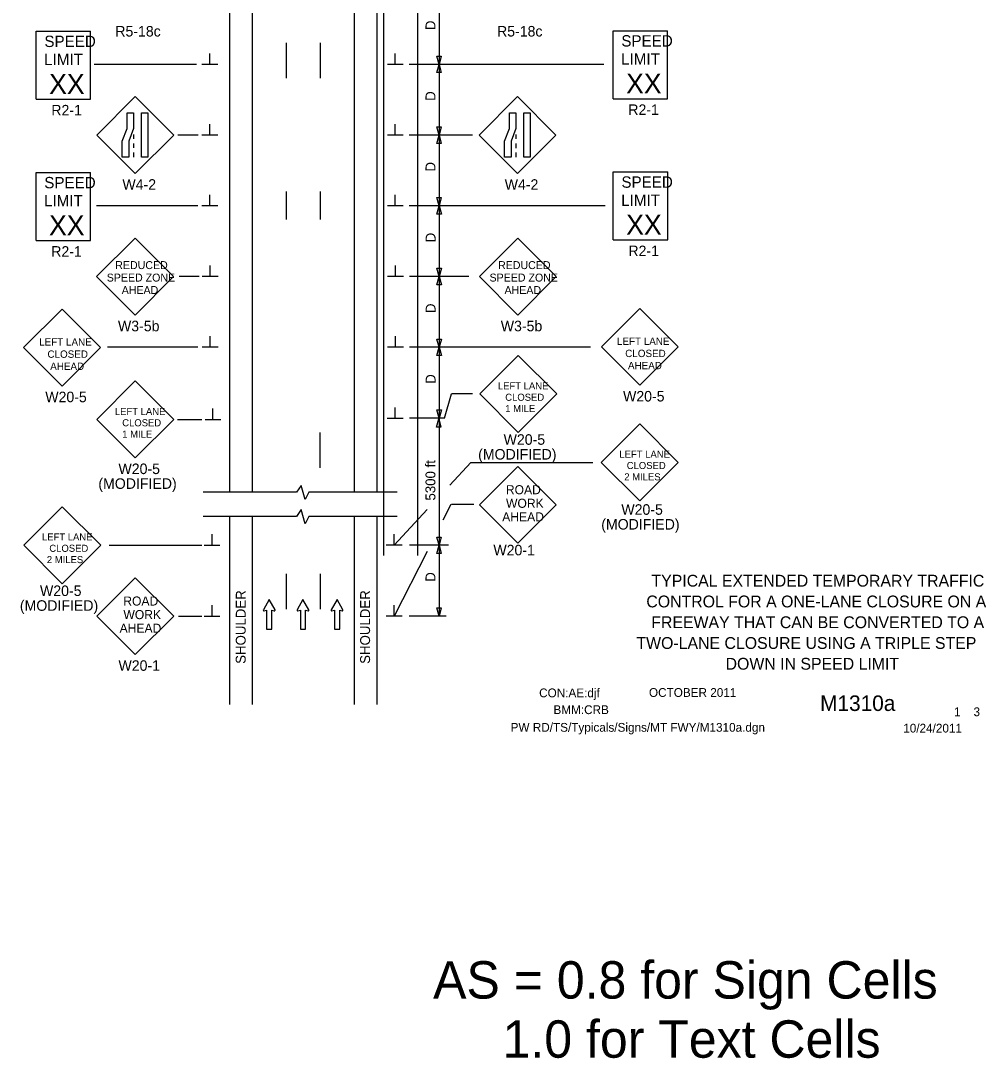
# Model space of a CAD drawing. Extents: x 16724 to 19508, y 5703 to 6974.
# Drawn here: x 16724 to 17407, y 5703 to 6436 of the extents above; entities that cross this region are included whole.
import ezdxf

# ---------------------------------------------------------------- set-up
doc = ezdxf.new("R2010")
doc.units = 0
for name, color, linetype in [('ALI_LEGAL_EX', 7, 'Continuous'), ('BORDER', 7, 'Continuous'), ('BORDER_SIGNAL_WO', 7, 'Continuous'), ('Level 3', 7, 'Continuous'), ('MT_SCRATCH_LEVEL_E', 7, 'Continuous'), ('PAVT_EDGE_EX', 7, 'Continuous'), ('TRAFFIC_SIGNS_PR', 7, 'Continuous'), ('TYPICAL_TEXT_DIMEN_PR', 7, 'Continuous')]:
    doc.layers.add(name, color=color, linetype=linetype)

msp = doc.modelspace()

# ---------------------------------------------------------------- linework, layer by layer
at = {"layer": 'ALI_LEGAL_EX'}
for p, q in [((16980.68, 6974.12), (16980.68, 6155.98)), ((17004.68, 6974.12), (17004.68, 6155.98)), ((16980.68, 6922.21), (16980.68, 6058.3)), ((17004.68, 6922.21), (17004.68, 6058.3))]:
    msp.add_line(p, q, dxfattribs=at)
for points in [[(16911.96, 6420.69), (16911.96, 6395.69)], [(16935.96, 6420.69), (16935.96, 6395.69)], [(16911.96, 6315.64), (16911.96, 6295.69)], [(16935.96, 6315.64), (16935.96, 6295.69)], [(16935.96, 6120.25), (16935.96, 6145.25)], [(16911.96, 6045.25), (16911.96, 6020.25)], [(16935.96, 6045.25), (16935.96, 6020.25)]]:
    msp.add_lwpolyline(points, dxfattribs=at)
at = {"layer": 'Level 3'}
msp.add_line((17023.76, 6155.41), (17028.75, 6172.5), dxfattribs=at)
at = {"layer": 'MT_SCRATCH_LEVEL_E'}
for p, q in [((16899.96, 6027.15), (16895.85, 6019.91)), ((16904.1, 6019.91), (16899.96, 6027.15)), ((16923.86, 6027.15), (16919.75, 6019.91)), ((16928.01, 6019.91), (16923.86, 6027.15)), ((16947.91, 6027.15), (16943.8, 6019.91)), ((16952.06, 6019.91), (16947.91, 6027.15)), ((16896.33, 6019.23), (16898.1, 6019.54)), ((16898.1, 6019.54), (16898.1, 6006.28)), ((16901.85, 6006.28), (16901.85, 6019.54)), ((16901.85, 6019.54), (16903.62, 6019.23)), ((16920.23, 6019.23), (16922.01, 6019.54)), ((16922.01, 6019.54), (16922.01, 6006.28)), ((16925.75, 6006.28), (16925.75, 6019.54)), ((16925.75, 6019.54), (16927.53, 6019.23)), ((16944.28, 6019.23), (16946.06, 6019.54)), ((16946.06, 6019.54), (16946.06, 6006.28)), ((16949.8, 6006.28), (16949.8, 6019.54)), ((16949.8, 6019.54), (16951.58, 6019.23)), ((16898.1, 6006.28), (16901.85, 6006.28)), ((16922.01, 6006.28), (16925.75, 6006.28)), ((16946.06, 6006.28), (16949.8, 6006.28))]:
    msp.add_line(p, q, dxfattribs=at)
for centre, start, end in [((16896.25, 6019.68), 150.42484, 279.96381), ((16903.69, 6019.68), 260.03619, 29.77312), ((16920.16, 6019.68), 150.42484, 279.96381), ((16927.6, 6019.68), 260.03619, 29.77312), ((16944.21, 6019.68), 150.42484, 279.96381), ((16951.65, 6019.68), 260.03619, 29.77312)]:
    msp.add_arc(centre, 0.463, start, end, dxfattribs=at)
at = {"layer": 'PAVT_EDGE_EX'}
for p, q in [((16871.96, 6927.73), (16871.96, 6180.21)), ((16887.96, 6927.73), (16887.96, 6180.21)), ((16959.96, 6927.73), (16959.96, 6180.21)), ((16975.96, 6927.73), (16975.96, 6180.21)), ((16871.96, 6180.21), (16871.96, 6103.04)), ((16887.96, 6180.21), (16887.96, 6103.06)), ((16959.96, 6180.21), (16959.96, 6103.06)), ((16975.96, 6180.21), (16975.96, 6103.06)), ((16871.96, 6085.92), (16871.96, 5952.9)), ((16887.96, 6085.92), (16887.96, 5952.9)), ((16959.96, 6085.92), (16959.96, 5952.9)), ((16975.96, 6085.92), (16975.96, 5952.9))]:
    msp.add_line(p, q, dxfattribs=at)
at = {"layer": 'TRAFFIC_SIGNS_PR'}
for p, q in [((16735.39, 6428.82), (16773.84, 6428.82)), ((16735.39, 6380.76), (16735.39, 6428.82)), ((16773.84, 6380.76), (16773.84, 6428.82)), ((17143.01, 6429.16), (17181.45, 6429.16)), ((17143.01, 6381.1), (17143.01, 6429.16)), ((17181.45, 6381.1), (17181.45, 6429.16)), ((16735.39, 6380.76), (16773.84, 6380.76)), ((16805.32, 6382.63), (16778.14, 6355.44)), ((16832.51, 6355.44), (16805.32, 6382.63)), ((17075.42, 6382.59), (17048.23, 6355.4)), ((17102.6, 6355.4), (17075.42, 6382.59)), ((17143.01, 6381.1), (17181.45, 6381.1)), ((16778.14, 6355.44), (16805.32, 6328.26)), ((16804.07, 6355.93), (16804.07, 6352.73)), ((16805.32, 6328.26), (16832.51, 6355.44)), ((17048.23, 6355.4), (17075.42, 6328.22)), ((17074.17, 6355.89), (17074.17, 6352.69)), ((17075.42, 6328.22), (17102.6, 6355.4)), ((16804.07, 6349.53), (16804.07, 6346.32)), ((16804.07, 6343.12), (16804.07, 6339.91)), ((17074.17, 6349.49), (17074.17, 6346.28)), ((17074.17, 6343.08), (17074.17, 6339.87)), ((16735.31, 6328.98), (16773.76, 6328.98)), ((16735.31, 6280.91), (16735.31, 6328.98)), ((16773.76, 6280.91), (16773.76, 6328.98)), ((17143.07, 6329.36), (17181.52, 6329.36)), ((17143.07, 6281.3), (17143.07, 6329.36)), ((17181.52, 6281.3), (17181.52, 6329.36)), ((16735.31, 6280.91), (16773.76, 6280.91)), ((16805.19, 6282.58), (16778, 6255.4)), ((16832.38, 6255.4), (16805.19, 6282.58)), ((17075.64, 6282.58), (17048.45, 6255.4)), ((17102.83, 6255.4), (17075.64, 6282.58)), ((17143.07, 6281.3), (17181.52, 6281.3)), ((16778, 6255.4), (16805.19, 6228.21)), ((16805.19, 6228.21), (16832.38, 6255.4)), ((17048.45, 6255.4), (17075.64, 6228.21)), ((17075.64, 6228.21), (17102.83, 6255.4)), ((16753.63, 6232.36), (16726.48, 6205.21)), ((16780.78, 6205.21), (16753.63, 6232.36)), ((17161.81, 6232.87), (17134.65, 6205.72)), ((17188.96, 6205.72), (17161.81, 6232.87)), ((16726.48, 6205.21), (16753.63, 6178.06)), ((16753.63, 6178.06), (16780.78, 6205.21)), ((17134.65, 6205.72), (17161.81, 6178.56)), ((17161.81, 6178.56), (17188.96, 6205.72)), ((17075.92, 6199.69), (17048.73, 6172.5)), ((17103.1, 6172.5), (17075.92, 6199.69)), ((16805.33, 6181.65), (16778.14, 6154.46)), ((16832.52, 6154.46), (16805.33, 6181.65)), ((17048.73, 6172.5), (17075.92, 6145.32)), ((17075.92, 6145.32), (17103.1, 6172.5)), ((16778.14, 6154.46), (16805.33, 6127.28)), ((16805.33, 6127.28), (16832.52, 6154.46)), ((17161.77, 6151.23), (17134.58, 6124.04)), ((17188.96, 6124.04), (17161.77, 6151.23)), ((17134.58, 6124.04), (17161.77, 6096.86)), ((17161.77, 6096.86), (17188.96, 6124.04)), ((17075.64, 6121.2), (17048.49, 6094.04)), ((17102.79, 6094.04), (17075.64, 6121.2)), ((17048.49, 6094.04), (17075.64, 6066.89)), ((17075.64, 6066.89), (17102.79, 6094.04)), ((16753.83, 6092.71), (16726.64, 6065.53)), ((16781.01, 6065.53), (16753.83, 6092.71)), ((16726.64, 6065.53), (16753.83, 6038.34)), ((16753.83, 6038.34), (16781.01, 6065.53)), ((16805.34, 6042.51), (16778.19, 6015.35)), ((16832.5, 6015.35), (16805.34, 6042.51)), ((16778.19, 6015.35), (16805.34, 5988.2)), ((16805.34, 5988.2), (16832.5, 6015.35))]:
    msp.add_line(p, q, dxfattribs=at)
for points in [[(16804.07, 6371.2), (16804.07, 6360), (16800.73, 6351.11), (16800.73, 6339.91), (16796.23, 6339.91), (16796.23, 6351.11), (16799.57, 6360), (16799.57, 6371.2)], [(16814.22, 6371.2), (16814.22, 6339.91), (16809.72, 6339.91), (16809.72, 6371.2)], [(17074.17, 6371.16), (17074.17, 6359.96), (17070.82, 6351.07), (17070.82, 6339.87), (17066.32, 6339.87), (17066.32, 6351.07), (17069.67, 6359.96), (17069.67, 6371.16)], [(17084.32, 6371.16), (17084.32, 6339.87), (17079.82, 6339.87), (17079.82, 6371.16)]]:
    msp.add_lwpolyline(points, close=True, dxfattribs=at)
at = {"layer": 'TYPICAL_TEXT_DIMEN_PR'}
for p, q in [((17019.96, 6455.41), (17019.96, 6405.41)), ((16858.07, 6405.41), (16858.07, 6413.19)), ((16989.08, 6405.41), (16989.08, 6413.19)), ((17019.96, 6405.41), (17018.39, 6411.27)), ((17018.39, 6411.27), (17019.96, 6411.27)), ((17019.96, 6411.27), (17021.53, 6411.27)), ((17021.53, 6411.27), (17019.96, 6405.41)), ((16848.73, 6405.41), (16776.3, 6405.41)), ((16863.7, 6405.41), (16852.45, 6405.41)), ((16994.71, 6405.41), (16983.46, 6405.41)), ((17027.77, 6405.41), (16998.96, 6405.41)), ((17018.39, 6399.55), (17019.96, 6405.41)), ((17019.96, 6405.41), (17019.96, 6355.41)), ((17019.96, 6405.41), (17021.53, 6399.55)), ((17136.33, 6405.41), (17027.77, 6405.41)), ((17019.96, 6399.55), (17018.39, 6399.55)), ((17021.53, 6399.55), (17019.96, 6399.55)), ((16858.07, 6355.41), (16858.07, 6363.19)), ((16989.08, 6355.41), (16989.08, 6363.19)), ((17019.96, 6355.41), (17018.39, 6361.27)), ((17018.39, 6361.27), (17019.96, 6361.27)), ((17019.96, 6361.27), (17021.53, 6361.27)), ((17021.53, 6361.27), (17019.96, 6355.41)), ((16849.89, 6355.41), (16835.47, 6355.41)), ((16863.7, 6355.41), (16852.45, 6355.41)), ((16994.71, 6355.41), (16983.46, 6355.41)), ((17027.77, 6355.41), (16998.96, 6355.41)), ((17018.39, 6349.55), (17019.96, 6355.41)), ((17019.96, 6355.41), (17019.96, 6305.41)), ((17019.96, 6355.41), (17021.53, 6349.55)), ((17043.6, 6355.41), (17027.77, 6355.41)), ((17019.96, 6349.55), (17018.39, 6349.55)), ((17021.53, 6349.55), (17019.96, 6349.55)), ((16858.07, 6305.41), (16858.07, 6313.19)), ((16989.08, 6305.41), (16989.08, 6313.19)), ((17019.96, 6305.41), (17018.39, 6311.27)), ((17018.39, 6311.27), (17019.96, 6311.27)), ((17019.96, 6311.27), (17021.53, 6311.27)), ((17021.53, 6311.27), (17019.96, 6305.41)), ((16849.6, 6305.41), (16777.95, 6305.41)), ((16863.7, 6305.41), (16852.45, 6305.41)), ((16994.71, 6305.41), (16983.46, 6305.41)), ((17027.77, 6305.41), (16998.96, 6305.41)), ((17018.52, 6299.55), (17020.09, 6305.41)), ((17020.09, 6299.55), (17018.52, 6299.55)), ((17020.09, 6305.41), (17020.09, 6255.41)), ((17020.09, 6305.41), (17021.66, 6299.55)), ((17021.66, 6299.55), (17020.09, 6299.55)), ((17137.25, 6305.41), (17027.77, 6305.41)), ((16858.21, 6255.41), (16858.21, 6263.19)), ((16989.22, 6255.41), (16989.22, 6263.19)), ((16850.42, 6255.41), (16836.41, 6255.41)), ((16863.83, 6255.41), (16852.58, 6255.41)), ((16994.84, 6255.41), (16983.59, 6255.41)), ((17027.77, 6255.41), (16999.09, 6255.41)), ((17020.09, 6255.41), (17018.52, 6261.27)), ((17018.52, 6261.27), (17020.09, 6261.27)), ((17018.52, 6249.55), (17020.09, 6255.41)), ((17020.09, 6261.27), (17021.66, 6261.27)), ((17021.66, 6261.27), (17020.09, 6255.41)), ((17020.09, 6255.41), (17020.09, 6205.41)), ((17020.09, 6255.41), (17021.66, 6249.55)), ((17040.96, 6255.41), (17027.77, 6255.41)), ((17020.09, 6249.55), (17018.52, 6249.55)), ((17021.66, 6249.55), (17020.09, 6249.55)), ((16858.21, 6205.41), (16858.21, 6213.19)), ((16989.22, 6205.41), (16989.22, 6213.19)), ((17020.09, 6205.41), (17018.52, 6211.27)), ((17018.52, 6211.27), (17020.09, 6211.27)), ((17020.09, 6211.27), (17021.66, 6211.27)), ((17021.66, 6211.27), (17020.09, 6205.41)), ((16849.51, 6205.41), (16785.69, 6205.41)), ((16863.83, 6205.41), (16852.58, 6205.41)), ((16994.84, 6205.41), (16983.59, 6205.41)), ((17027.77, 6205.41), (16999.09, 6205.41)), ((17018.52, 6199.55), (17020.09, 6205.41)), ((17020.09, 6205.41), (17020.09, 6155.41)), ((17020.09, 6205.41), (17021.66, 6199.55)), ((17127.09, 6205.41), (17027.77, 6205.41)), ((17020.09, 6199.55), (17018.52, 6199.55)), ((17021.66, 6199.55), (17020.09, 6199.55)), ((17043.57, 6172.5), (17028.75, 6172.5)), ((16860.27, 6154.5), (16860.27, 6162.28)), ((16989.05, 6155.07), (16989.05, 6162.85)), ((17020.09, 6155.41), (17018.52, 6161.27)), ((17018.52, 6161.27), (17020.09, 6161.27)), ((17020.09, 6161.27), (17021.66, 6161.27)), ((17021.66, 6161.27), (17020.09, 6155.41)), ((16835.24, 6154.5), (16852.43, 6154.5)), ((16854.64, 6154.5), (16865.89, 6154.5)), ((16994.67, 6155.07), (16983.42, 6155.07)), ((17023.76, 6155.41), (16999.09, 6155.41)), ((17018.22, 6149), (17019.79, 6154.86)), ((17019.79, 6154.86), (17021.36, 6149)), ((17019.96, 6155.41), (17019.96, 6065.48)), ((17019.79, 6149), (17018.22, 6149)), ((17021.36, 6149), (17019.79, 6149)), ((17027.71, 6108.01), (17042.51, 6124)), ((17042.51, 6124), (17128.69, 6124)), ((16919.31, 6103.04), (16853.36, 6103.04)), ((16922.56, 6107.84), (16919.31, 6103.04)), ((16925.3, 6097.9), (16922.56, 6107.84)), ((16928.05, 6103.04), (16925.3, 6097.9)), ((16990.38, 6103.04), (16928.05, 6103.04)), ((17028.38, 6094.23), (17022.75, 6083.16)), ((17044.62, 6094.23), (17028.8, 6094.23)), ((16922.56, 6090.71), (16919.31, 6085.91)), ((16925.3, 6080.77), (16922.56, 6090.71)), ((16988.33, 6065.48), (17011.66, 6090.68)), ((16919.31, 6085.91), (16853.36, 6085.91)), ((16928.05, 6085.91), (16925.3, 6080.77)), ((16990.38, 6085.91), (16928.05, 6085.91)), ((16859.58, 6065.48), (16859.58, 6073.27)), ((16988.33, 6065.48), (16988.33, 6073.27)), ((16786.86, 6065.48), (16852.43, 6065.48)), ((16853.96, 6065.48), (16865.21, 6065.48)), ((16993.96, 6065.48), (16982.71, 6065.48)), ((17026.57, 6065.48), (16999.09, 6065.48)), ((17019.96, 6065.48), (17018.39, 6071.34)), ((17018.39, 6071.34), (17019.96, 6071.34)), ((17018.39, 6059.62), (17019.96, 6065.48)), ((17019.96, 6071.34), (17021.53, 6071.34)), ((17021.53, 6071.34), (17019.96, 6065.48)), ((17019.96, 6065.48), (17019.96, 6015.48)), ((17019.96, 6065.48), (17021.53, 6059.62)), ((17011.5, 6061.03), (16988.33, 6015.48)), ((17019.96, 6059.62), (17018.39, 6059.62)), ((17021.53, 6059.62), (17019.96, 6059.62)), ((16859.58, 6015.48), (16859.58, 6023.27)), ((16988.33, 6015.48), (16988.33, 6023.27)), ((17019.96, 6015.48), (17018.39, 6021.34)), ((17018.39, 6021.34), (17019.96, 6021.34)), ((17019.96, 6021.34), (17021.53, 6021.34)), ((17021.53, 6021.34), (17019.96, 6015.48)), ((16835.9, 6015.48), (16852.43, 6015.48)), ((16853.96, 6015.48), (16865.21, 6015.48)), ((16993.96, 6015.48), (16982.71, 6015.48)), ((17024.96, 6015.48), (16998.96, 6015.48))]:
    msp.add_line(p, q, dxfattribs=at)

# ---------------------------------------------------------------- texts
at = {"layer": 'BORDER'}
for s, p in [('TYPICAL EXTENDED TEMPORARY TRAFFIC', (17170.06, 6036.26)), ('CONTROL FOR A ONE-LANE CLOSURE ON A', (17166.43, 6021.59)), ('FREEWAY THAT CAN BE CONVERTED TO A', (17169.93, 6006.91)), ('TWO-LANE CLOSURE USING A TRIPLE STEP ', (17159.43, 5992.23)), ('DOWN IN SPEED LIMIT', (17222.43, 5977.56))]:
    msp.add_text(s, height=8.3734, dxfattribs=at).set_placement(p)
at = {"layer": 'BORDER_SIGNAL_WO'}
for s, height, p in [('CON:AE:djf  ', 6.2, (17090.69, 5958.06)), ('    OCTOBER 2011    ', 6.2, (17159.08, 5958.34)), ('    M1310a   ', 11, (17272.86, 5948.38)), ('BMM:CRB   ', 6.2, (17100.81, 5946.17)), (' 1    3 ', 6.2, (17381.45, 5944.7)), ('PW RD/TS/Typicals/Signs/MT FWY/M1310a.dgn      ', 6.2, (17070.55, 5933.71)), ('10/24/2011    ', 6.2, (17347.93, 5933.13)), ('AS = 0.8 for Sign Cells', 26.4241, (17015.79, 5745.09)), ('     1.0 for Text Cells', 26.4241, (17015.79, 5703.3))]:
    msp.add_text(s, height=height, dxfattribs=at).set_placement(p)
at = {"layer": 'TRAFFIC_SIGNS_PR'}
for s, height, p in [('R5-18c', 7.44, (16791.28, 6425.09)), ('R5-18c', 7.44, (17060.98, 6425.09)), ('SPEED', 8.01, (16741.17, 6417.67)), ('SPEED', 8.01, (17148.78, 6418.01)), ('LIMIT', 8.01, (16741.01, 6404.86)), ('LIMIT', 8.01, (17148.62, 6405.2)), ('XX', 14.048, (16744.52, 6384.53)), ('XX', 14.048, (17152.13, 6384.87)), ('R2-1', 7.449, (16746.08, 6369.31)), ('R2-1', 7.449, (17153.7, 6369.65)), ('SPEED', 8.01, (16741.09, 6317.82)), ('W4-2', 7.449, (16796.27, 6316.8)), ('W4-2', 7.449, (17066.36, 6316.76)), ('SPEED', 8.01, (17148.84, 6318.21)), ('LIMIT', 8.01, (16740.93, 6305.01)), ('LIMIT', 8.01, (17148.68, 6305.4)), ('XX', 14.048, (17152.19, 6285.07)), ('XX', 14.048, (16744.44, 6284.68)), ('R2-1', 7.449, (17153.76, 6269.85)), ('R2-1', 7.449, (16746, 6269.46)), ('REDUCED', 5.607, (16791.23, 6260.71)), ('REDUCED', 5.607, (17061.68, 6260.71)), ('SPEED ZONE', 5.607, (16785.21, 6251.9)), ('SPEED ZONE', 5.607, (17055.66, 6251.9)), ('AHEAD', 5.607, (16795.79, 6243.09)), ('AHEAD', 5.607, (17066.24, 6243.09)), ('W3-5b', 7.449, (16793.13, 6216.75)), ('W3-5b', 7.449, (17063.58, 6216.76)), ('LEFT LANE', 5.2, (16737.51, 6206.61)), ('LEFT LANE', 5.2, (17145.69, 6207.11)), ('CLOSED', 5.2, (17151.52, 6198.51)), ('CLOSED', 5.2, (16743.34, 6198.01)), ('AHEAD', 5.2, (16745.29, 6189.41)), ('AHEAD', 5.2, (17153.46, 6189.91)), ('LEFT LANE', 5.006, (17061.53, 6175.63)), ('W20-5', 7.44, (17149.98, 6167.12)), ('W20-5', 7.44, (16741.8, 6166.62)), ('CLOSED', 5.006, (17066.74, 6167.62)), ('LEFT LANE', 5.006, (16790.94, 6157.59)), ('1 MILE', 5.006, (17066.74, 6159.61)), ('CLOSED', 5.006, (16796.15, 6149.58)), ('1 MILE', 5.006, (16796.15, 6141.57)), ('W20-5 ', 7.449, (17065.59, 6136.53)), ('(MODIFIED) ', 7.4493, (17047.61, 6126.08)), ('LEFT LANE', 5.006, (17147.38, 6127.39)), ('W20-5', 7.449, (16793.49, 6115.82)), ('CLOSED', 5.006, (17152.59, 6119.39)), ('2 MILES', 5.006, (17150.84, 6111.38)), ('(MODIFIED)', 7.449, (16779.29, 6105.37)), ('ROAD', 6.4, (17067.18, 6101.58)), ('WORK', 6.4, (17067.29, 6091.98)), ('W20-5', 7.449, (17148.77, 6087.05)), ('AHEAD', 6.4, (17064.6, 6082.38)), ('(MODIFIED)', 7.449, (17134.58, 6076.6)), ('LEFT LANE', 5.006, (16739.43, 6068.88)), ('CLOSED', 5.006, (16744.65, 6060.87)), ('W20-1', 7.44, (17058.37, 6058.38)), ('2 MILES', 5.006, (16742.9, 6052.86)), ('W20-5', 7.449, (16738.05, 6029.63)), ('ROAD', 6.4, (16796.89, 6022.89)), ('(MODIFIED)', 7.449, (16723.85, 6019.18)), ('WORK', 6.4, (16796.99, 6013.29)), ('AHEAD', 6.4, (16794.3, 6003.69)), ('W20-1', 7.44, (16793.51, 5976.76))]:
    msp.add_text(s, height=height, dxfattribs=at).set_placement(p)
at = {"layer": 'TYPICAL_TEXT_DIMEN_PR'}
for s, p in [('D', (17017.4, 6429.63)), ('D', (17017.4, 6379.63)), ('D', (17017.4, 6329.63)), ('D', (17017.54, 6279.63)), ('D', (17017.54, 6229.63)), ('D', (17017.54, 6179.63)), ('5300 ft', (17017.4, 6097.09)), ('D', (17017.4, 6039.7)), ('SHOULDER', (16883.38, 5981.7)), ('SHOULDER', (16971.24, 5981.7))]:
    msp.add_text(s, height=7, rotation=90, dxfattribs=at).set_placement(p)

doc.saveas('drawing.dxf')
